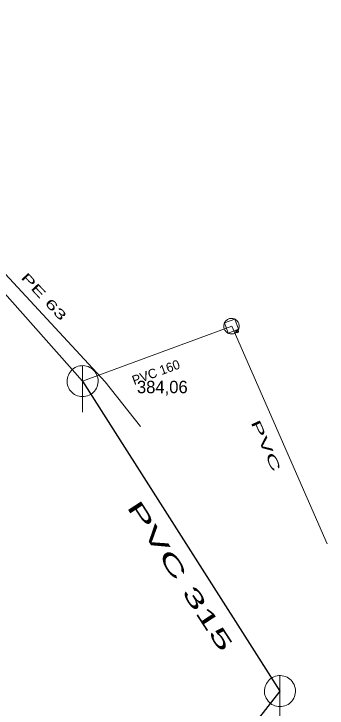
# Model space of a CAD drawing. Extents: x -809028 to -807737, y -990545 to -989489.
# Drawn here: x -808066.11 to -808045.91, y -989913.54 to -989868.81 of the extents above; entities that cross this region are included whole.
import ezdxf

# ---------------------------------------------------------------- set-up
doc = ezdxf.new("R2010")
doc.units = 0
doc.header["$LTSCALE"] = 0.32
doc.header["$PDMODE"] = 32
doc.header["$PDSIZE"] = 0.16
for name, color, linetype, lineweight in [('1', 7, 'Continuous', 13), ('11', 7, 'Continuous', 13), ('13', 7, 'Continuous', 13), ('14', 7, 'Continuous', 25), ('22', 7, 'Continuous', 13)]:
    doc.layers.add(name, color=color, linetype=linetype, lineweight=lineweight)

msp = doc.modelspace()

# ---------------------------------------------------------------- linework, layer by layer
at = {"layer": '11'}
msp.add_lwpolyline([(-808045.906, -989902.96), (-808052.044, -989888.925), (-808061.68, -989892.469)], dxfattribs=at)
at = {"layer": '13'}
msp.add_lwpolyline([(-808069.925, -989882.077), (-808060.23, -989892.508), (-808057.94, -989895.383)], dxfattribs=at)
at = {"layer": '14'}
for p, q in [((-808061.68, -989892.469), (-808048.949, -989912.44)), ((-808048.949, -989912.44), (-808053.289, -989917.92))]:
    msp.add_line(p, q, dxfattribs=at)
msp.add_lwpolyline([(-808089.359, -989861.309), (-808075.59, -989876.809), (-808061.68, -989892.469)], dxfattribs=at)
at = {"layer": '22'}
for p, q in [((-808061.68, -989894.469), (-808061.679, -989891.469)), ((-808048.949, -989914.44), (-808048.948, -989911.44))]:
    msp.add_line(p, q, dxfattribs=at)
for points in [[(-808051.606, -989888.755), (-808051.626, -989888.707), (-808051.654, -989888.66), (-808051.683, -989888.618), (-808051.717, -989888.578), (-808051.755, -989888.543), (-808051.799, -989888.511), (-808051.843, -989888.485), (-808051.891, -989888.464), (-808051.939, -989888.446), (-808051.991, -989888.434), (-808052.044, -989888.428), (-808052.095, -989888.428), (-808052.147, -989888.431), (-808052.2, -989888.442), (-808052.248, -989888.459), (-808052.296, -989888.479), (-808052.343, -989888.505), (-808052.386, -989888.535), (-808052.425, -989888.569), (-808052.459, -989888.608), (-808052.491, -989888.65), (-808052.518, -989888.695), (-808052.54, -989888.743), (-808052.557, -989888.791), (-808052.568, -989888.842), (-808052.574, -989888.895), (-808052.575, -989888.947), (-808052.571, -989888.999), (-808052.559, -989889.051), (-808052.544, -989889.099), (-808052.523, -989889.147), (-808052.497, -989889.194), (-808052.468, -989889.238), (-808052.433, -989889.276), (-808052.395, -989889.311), (-808052.353, -989889.344), (-808052.308, -989889.37), (-808052.261, -989889.392), (-808052.211, -989889.408), (-808052.16, -989889.421), (-808052.107, -989889.426), (-808052.056, -989889.427), (-808052.003, -989889.423), (-808051.952, -989889.411), (-808051.903, -989889.396), (-808051.855, -989889.376), (-808051.809, -989889.349), (-808051.766, -989889.32), (-808051.727, -989889.285), (-808051.691, -989889.246), (-808051.659, -989889.205), (-808051.633, -989889.161), (-808051.612, -989889.113), (-808051.594, -989889.063), (-808051.582, -989889.012), (-808051.576, -989888.959), (-808051.575, -989888.908), (-808051.58, -989888.856), (-808051.591, -989888.803)], [(-808052.525, -989888.72), (-808051.861, -989888.474), (-808051.62, -989889.125), (-808052.286, -989889.37)], [(-808060.68, -989892.469), (-808060.685, -989892.36), (-808060.703, -989892.252), (-808060.733, -989892.146), (-808060.773, -989892.045), (-808060.825, -989891.948), (-808060.887, -989891.858), (-808060.959, -989891.775), (-808061.039, -989891.701), (-808061.127, -989891.635), (-808061.221, -989891.58), (-808061.321, -989891.535), (-808061.426, -989891.502), (-808061.533, -989891.48), (-808061.642, -989891.47), (-808061.752, -989891.472), (-808061.86, -989891.486), (-808061.967, -989891.511), (-808062.07, -989891.548), (-808062.168, -989891.597), (-808062.26, -989891.655), (-808062.346, -989891.724), (-808062.423, -989891.801), (-808062.492, -989891.887), (-808062.551, -989891.979), (-808062.599, -989892.077), (-808062.636, -989892.18), (-808062.662, -989892.287), (-808062.676, -989892.395), (-808062.679, -989892.505), (-808062.669, -989892.614), (-808062.648, -989892.721), (-808062.614, -989892.825), (-808062.57, -989892.925), (-808062.515, -989893.02), (-808062.449, -989893.108), (-808062.375, -989893.188), (-808062.292, -989893.26), (-808062.202, -989893.322), (-808062.106, -989893.374), (-808062.004, -989893.415), (-808061.899, -989893.445), (-808061.791, -989893.463), (-808061.681, -989893.469), (-808061.572, -989893.463), (-808061.464, -989893.445), (-808061.359, -989893.416), (-808061.257, -989893.375), (-808061.16, -989893.323), (-808061.07, -989893.261), (-808060.987, -989893.19), (-808060.912, -989893.11), (-808060.847, -989893.022), (-808060.791, -989892.928), (-808060.747, -989892.828), (-808060.713, -989892.724), (-808060.691, -989892.616), (-808060.681, -989892.507)], [(-808047.949, -989912.44), (-808047.954, -989912.331), (-808047.972, -989912.223), (-808048.002, -989912.117), (-808048.042, -989912.016), (-808048.094, -989911.919), (-808048.156, -989911.829), (-808048.228, -989911.746), (-808048.308, -989911.672), (-808048.396, -989911.606), (-808048.49, -989911.551), (-808048.59, -989911.506), (-808048.695, -989911.473), (-808048.802, -989911.451), (-808048.911, -989911.441), (-808049.021, -989911.443), (-808049.129, -989911.457), (-808049.236, -989911.482), (-808049.339, -989911.519), (-808049.437, -989911.568), (-808049.529, -989911.626), (-808049.615, -989911.695), (-808049.692, -989911.772), (-808049.761, -989911.858), (-808049.82, -989911.95), (-808049.868, -989912.048), (-808049.905, -989912.151), (-808049.931, -989912.258), (-808049.945, -989912.366), (-808049.948, -989912.476), (-808049.938, -989912.585), (-808049.917, -989912.692), (-808049.883, -989912.796), (-808049.839, -989912.896), (-808049.784, -989912.991), (-808049.718, -989913.079), (-808049.644, -989913.159), (-808049.561, -989913.231), (-808049.471, -989913.293), (-808049.375, -989913.345), (-808049.273, -989913.386), (-808049.168, -989913.416), (-808049.06, -989913.434), (-808048.95, -989913.44), (-808048.841, -989913.434), (-808048.733, -989913.416), (-808048.628, -989913.387), (-808048.526, -989913.346), (-808048.429, -989913.294), (-808048.339, -989913.232), (-808048.256, -989913.161), (-808048.181, -989913.081), (-808048.116, -989912.993), (-808048.06, -989912.899), (-808048.016, -989912.799), (-808047.982, -989912.695), (-808047.96, -989912.587), (-808047.95, -989912.478)]]:
    msp.add_lwpolyline(points, close=True, dxfattribs=at)
msp.add_point((-808051.71, -989889.27), dxfattribs=at)

# ---------------------------------------------------------------- texts
at = {"layer": '1'}
for s, height, rotation, width, p in [('PE 63 ', 0.6, 313, 1.75, (-808065.701, -989885.824)), ('PVC   ', 0.6, 294, 2.15, (-808050.85, -989895.125)), ('PVC 315 ', 1, 303, 2.1, (-808058.869, -989900.57))]:
    msp.add_text(s, height=height, rotation=rotation, dxfattribs=dict(at, width=width)).set_placement(p)
msp.add_text('PVC 160 ', height=0.6, rotation=20, dxfattribs=at).set_placement((-808058.352, -989892.727))
at = {"layer": '14'}
msp.add_text('384,06', height=0.8, dxfattribs=at).set_placement((-808058.173, -989893.246))

doc.saveas('drawing.dxf')
